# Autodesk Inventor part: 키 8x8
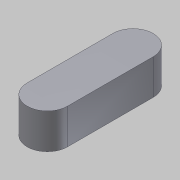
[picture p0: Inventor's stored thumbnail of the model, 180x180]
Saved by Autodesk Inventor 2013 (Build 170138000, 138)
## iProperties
Company: 한국ATC센터
Created: 2014-10
Part Number: 키 8x8
Document SubType Name: Modeling
Designer: 한국ATC센터
Density: 7.86 g/cm^3
Material: 강, 연강
Mass: 10.2483 g
Surface Area: 7.8646 cm^2
Volume: 1.30386 cm^3
Author: KYOUNG IL JANG
Revision Number: 1
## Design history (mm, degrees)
sketch "스케치1"
  geometry: L1 (28.264, -14)-(28.264, -31) reference; L2 (20.264, -31)-(20.264, -14) reference; A1 r 4 centre (24.264, -31) between (20.264, -31) and (28.264, -31) reference; A2 r 4 centre (24.264, -14) between (28.264, -14) and (20.264, -14) reference; 1 further point
extrude "돌출1" new body sketch "스케치1" distance "d0" = 7; taper "d1" = 0 deg
node "솔리드1"
node "참조1"
